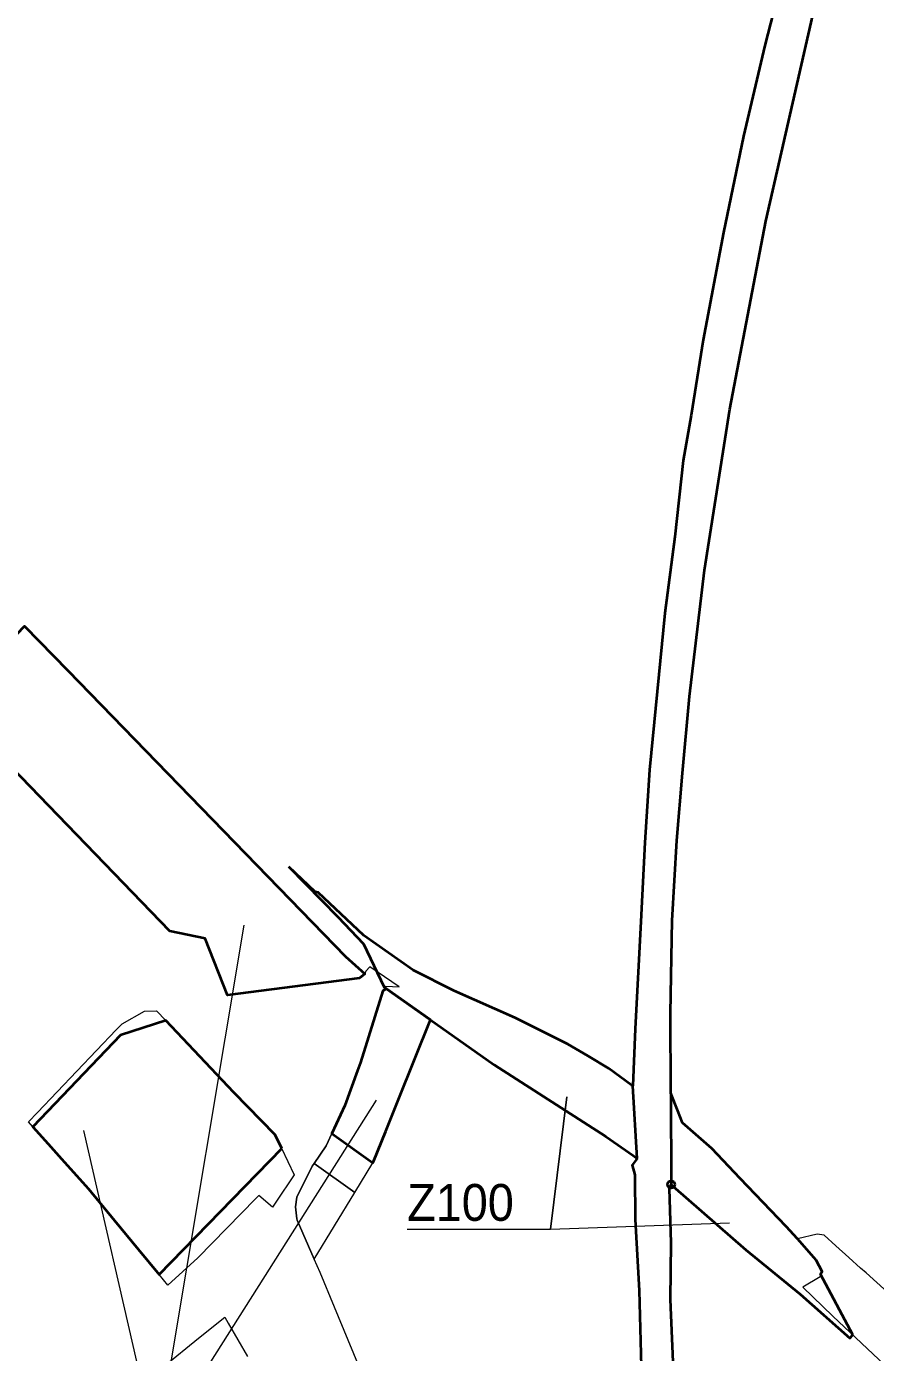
# Model space of a CAD drawing. Extents: x -650276 to -642489, y -1074425 to -1066658.
# Drawn here: x -645767 to -645214, y -1072612 to -1071749 of the extents above; entities that cross this region are included whole.
import ezdxf

# ---------------------------------------------------------------- set-up
doc = ezdxf.new("R2010")
doc.units = 0
doc.header["$LTSCALE"] = 9.6
doc.header["$PDMODE"] = 32
doc.header["$PDSIZE"] = 4.8
for name, color, linetype, lineweight in [('1', 7, 'Continuous', 13), ('44', 7, 'Continuous', 40), ('45', 7, 'Continuous', 40), ('46', 7, 'Continuous', 13)]:
    doc.layers.add(name, color=color, linetype=linetype, lineweight=lineweight)

msp = doc.modelspace()

# ---------------------------------------------------------------- linework, layer by layer
at = {"layer": '1'}
for points in [[(-645674, -1072338), (-645823, -1072184), (-645880.412, -1072243.358), (-645919.698, -1072210.262), (-645924.734, -1072214.99), (-646008.065, -1072293.22)], [(-645591.06, -1072511.06), (-645581.13, -1072491), (-645579.92, -1072489.22), (-645572.13, -1072477.78), (-645568.38, -1072469.68), (-645559.27, -1072449.65), (-645551.54, -1072428.66), (-645549.6, -1072423.39), (-645546.39, -1072412.63), (-645535.05, -1072376.72), (-645532.75, -1072375.41), (-645533.08, -1072373.71), (-645524.4, -1072374.2), (-645543.6, -1072361.08), (-645546.25, -1072364.1), (-645546.82, -1072365.72), (-645550.41, -1072368.47), (-645636.37, -1072379.57), (-645650.78, -1072342.73), (-645674, -1072338)], [(-645726.95, -1072505.7), (-645744.38, -1072486.18), (-645763.06, -1072465.26), (-645765.95, -1072462.03), (-645760.02, -1072455.94), (-645708.94, -1072402.11), (-645705, -1072398.19), (-645690.37, -1072390.13), (-645682.59, -1072389.76), (-645676.53, -1072396.16), (-645632.1, -1072442.93)], [(-645632.1, -1072442.93), (-645605.17, -1072470.52), (-645592.9, -1072496.52)], [(-645568.38, -1072469.68), (-645572.13, -1072477.78), (-645579.92, -1072489.22), (-645553.35, -1072508.1)], [(-645553.35, -1072508.1), (-645541.56, -1072488.74), (-645568.38, -1072469.68)], [(-645579.76, -1072551.45), (-645553.35, -1072508.1), (-645579.92, -1072489.22), (-645581.13, -1072491), (-645591.06, -1072511.06), (-645592.08, -1072517.43)], [(-645592.9, -1072496.52), (-645604.82, -1072514.3), (-645607.07, -1072517.61), (-645615.95, -1072510.16), (-645617.87, -1072512.12), (-645655.65, -1072550.62), (-645675.13, -1072568.36), (-645680.87, -1072561.42), (-645694.51, -1072544.93), (-645709.92, -1072526.3), (-645726.95, -1072505.7)], [(-645566.54, -1072582.88), (-645575.9, -1072560.13), (-645579.76, -1072551.45), (-645591.03, -1072526.14), (-645591.143, -1072525.2), (-645592.08, -1072517.43), (-645591.06, -1072511.06)], [(-645592.08, -1072517.43), (-645591.143, -1072525.2), (-645591.03, -1072526.14), (-645579.76, -1072551.45)], [(-645201.69, -1072577.19), (-645220.27, -1072560.51), (-645223.86, -1072557.28), (-645231.56, -1072550.37), (-645240, -1072542.79), (-645247.59, -1072535.97), (-645252.12, -1072535.29), (-645265.009, -1072538.358), (-645252.768, -1072552.178), (-645248.967, -1072559.511), (-645249.9, -1072561.25), (-645248.8, -1072562.32), (-645250.27, -1072563.1), (-645261.57, -1072569.842), (-645242, -1072588.6), (-645185.95, -1072641.32)], [(-645551.5, -1072619.44), (-645566.54, -1072582.88)], [(-645677.56, -1072621.1), (-645655.18, -1072603.04), (-645638.12, -1072589.27), (-645635.96, -1072593.24), (-645623.21, -1072614.93)]]:
    msp.add_lwpolyline(points, dxfattribs=at)
at = {"layer": '44'}
for points in [[(-645347.551, -1072443.527), (-645347.677, -1072391.355), (-645346.62, -1072330.914), (-645343.458, -1072278.998), (-645339.908, -1072235.158), (-645335.367, -1072185.207), (-645325.498, -1072102.789), (-645309.01, -1071998.147), (-645285.617, -1071875.733), (-645244.798, -1071696.585), (-645235.793, -1071663.703), (-645230.436, -1071634.261), (-645227.905, -1071625.277), (-645222.48, -1071606.08)], [(-645261.094, -1071645.025), (-645264.841, -1071657.687), (-645269.077, -1071687.396), (-645274.868, -1071717.176), (-645286.175, -1071761.228), (-645300.076, -1071820.179), (-645313.153, -1071883.081)], [(-645313.153, -1071883.081), (-645326.343, -1071952.807), (-645334.118, -1072001.954), (-645339.455, -1072031.565), (-645344.819, -1072081.225), (-645351.358, -1072130.815), (-645361.317, -1072232.824), (-645364.435, -1072280.268), (-645366.951, -1072331.609), (-645370.624, -1072401.447), (-645372.228, -1072438.764)], [(-645369.364, -1072485.931), (-645372.228, -1072438.764), (-645373.099, -1072438.135), (-645387.894, -1072427.453), (-645401.441, -1072419.033), (-645414.631, -1072411.611), (-645448.831, -1072394.325), (-645488.64, -1072376.782), (-645515.437, -1072363.447), (-645547.593, -1072340.827), (-645577.33, -1072312.704), (-645579.217, -1072312.425), (-645596.405, -1072296.114)], [(-645596.405, -1072296.114), (-645564.4, -1072328.61), (-645547.72, -1072346.19), (-645534.301, -1072374.332), (-645462.646, -1072425.015)], [(-645462.646, -1072425.015), (-645389.731, -1072471.612), (-645372.013, -1072484.069), (-645369.364, -1072485.931)], [(-645339.904, -1072462.677), (-645342.953, -1072455.042), (-645347.551, -1072443.527), (-645347.292, -1072502.877)], [(-645228.96, -1072600.865), (-645249.9, -1072561.25), (-645248.967, -1072559.511), (-645252.768, -1072552.178), (-645265.009, -1072538.358), (-645272.276, -1072530.154), (-645302.303, -1072499.014), (-645320.805, -1072479.495), (-645339.904, -1072462.677)], [(-645369.364, -1072485.931), (-645372.72, -1072490.314), (-645370.928, -1072496.619), (-645370.755, -1072525.734), (-645368.173, -1072571.881), (-645366.022, -1072654.462), (-645364.524, -1072682.575), (-645364.786, -1072692.977), (-645362.708, -1072714.781)], [(-645338.023, -1072755.969), (-645339.96, -1072721.587), (-645344.152, -1072658.857), (-645347.795, -1072577.893), (-645347.214, -1072540.97), (-645348.253, -1072505.583), (-645347.292, -1072502.877)], [(-645347.292, -1072502.877), (-645346.093, -1072503.921), (-645298.498, -1072545.352)], [(-645298.498, -1072545.352), (-645263.217, -1072574.314), (-645230.845, -1072602.888), (-645228.96, -1072600.865)]]:
    msp.add_lwpolyline(points, dxfattribs=at)
at = {"layer": '44', "lineweight": 13}
msp.add_lwpolyline([(-645519.31, -1072532.095), (-645425.882, -1072532.095), (-645415.202, -1072445.813), (-645425.882, -1072532.095), (-645309.26, -1072527.964)], dxfattribs=at)
msp.add_lwpolyline([(-645519.31, -1072532.095), (-645425.882, -1072532.095), (-645415.202, -1072445.813), (-645425.882, -1072532.095), (-645309.26, -1072527.964)], dxfattribs=at)
at = {"layer": '44'}
msp.add_point((-645347.292, -1072502.877), dxfattribs=at)
at = {"layer": '45'}
for points in [[(-645817.219, -1072189.975), (-645768.649, -1072139.283), (-645740.45, -1072168.23), (-645559.34, -1072354.42), (-645546.82, -1072365.72), (-645550.41, -1072368.47), (-645636.37, -1072379.57), (-645650.78, -1072342.73), (-645674, -1072338), (-645789.298, -1072218.833)], [(-645503.98, -1072395.64), (-645532.75, -1072375.41), (-645535.05, -1072376.72), (-645549.6, -1072423.39), (-645551.54, -1072428.66), (-645559.92, -1072451.41), (-645568.38, -1072469.68), (-645541.56, -1072488.74), (-645541.09, -1072487.98), (-645533.15, -1072468.21), (-645524.87, -1072447.61)], [(-645600.945, -1072479.473), (-645605.17, -1072470.52), (-645632.1, -1072442.93), (-645632.1, -1072442.93), (-645676.53, -1072396.16), (-645706.039, -1072405.769), (-645763.06, -1072465.26), (-645753.128, -1072476.383), (-645744.38, -1072486.18), (-645726.95, -1072505.7), (-645709.92, -1072526.3), (-645694.51, -1072544.93), (-645680.87, -1072561.42)]]:
    msp.add_lwpolyline(points, close=True, dxfattribs=at)
at = {"layer": '46'}
for q in [(-645625.498, -1072333.934), (-645539.175, -1072448), (-645729.938, -1072467.657)]:
    msp.add_line((-645682.434, -1072673.943), q, dxfattribs=at)

# ---------------------------------------------------------------- texts
at = {"layer": '44', "width": 0.95}
msp.add_text('Z100', height=24, dxfattribs=at).set_placement((-645519.262, -1072526.583))
msp.add_text('Z100', height=24, dxfattribs=at).set_placement((-645519.262, -1072526.583))

doc.saveas('drawing.dxf')
